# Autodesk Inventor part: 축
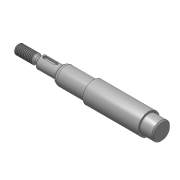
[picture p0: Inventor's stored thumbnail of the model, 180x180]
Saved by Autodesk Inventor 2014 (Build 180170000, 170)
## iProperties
Created: 2015-11
Part Number: 축
Material: 강철, 연강
Document SubType Name: Modeling
Designer: mduedu
Density: 1 g/cm^3
Appearance: Steel
Author: mduedu
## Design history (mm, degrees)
sketch "스케치1"
  geometry: L1 (-86, 0)-(86, 0); L2 (-86, 0)-(-86, 4); L3 (-86, 4)-(-70.732, 4); L4 (-70.732, 4)-(-69, 3); L5 (-69, 3)-(-67, 3); L6 (-67, 3)-(-67, 5); L7 (-67, 5)-(-49, 5); L8 (-49, 5)-(-49, 6.55); L9 (-47.355, 7.5)-(-23, 7.5); L10 (-23, 7.5)-(-23, 9); L11 (0, 0)-(0, 9); L12 (86, 4)-(70.732, 4); L13 (70.732, 4)-(69, 3); L14 (69, 3)-(67, 3); L15 (67, 3)-(67, 5); L16 (67, 5)-(49, 5); L17 (23, 7.5)-(23, 9); L18 (86, 0)-(86, 4); L19 (-23, 9)-(23, 9); L20 (-49, 6.55)-(-47.355, 7.5); L21 (47.355, 7.5)-(23, 7.5); L22 (49, 6.55)-(47.355, 7.5); L23 (49, 5)-(49, 6.55); 1 further point
  constraints: 46 end point, 10 symmetric about line, 6 perpendicular, 5 parallel, 2 midpoint, 1 coincident, 1 horizontal
  dimensions: "d0" = 172 distance of L1.start L1.end (derived); "d1" = 8 diameter of L3 L1; "d2" = 30 deg angle of L4 L5; "d3" = 6 diameter of L5 L1; "d4" = 10 diameter of L7 L1; "d5" = 15 diameter of L9 L1; "d6" = 18 diameter of L19 L1; "d8" = 18 distance of L6.end L7.end; "d9" = 46 distance of L10.end L17.end; "d10" = 2 distance of L4.end L5.end; "d11" = 17 distance from line of L4.end L2; "d16" = 13.1 diameter of L8.end L1; "d17" = 30 deg angle of L20 L9; "d18" = 26 distance between parallel lines of L10 L8
revolve "회전1" sketch "스케치1" stored, may be unused: angle "d12" = 90 deg
chamfer "모따기1" distance "d13" = 1; stored, may be unused: second distance "d14" = 2, angle "d15" = 45 deg
fillet "모깎기3" dims "d35" = 4
node "작업 평면1"
sketch "스케치2" dims "d23" = 12
  geometry: L1 (-5.5, 1.5)-(3.5, 1.5); L2 (3.5, 1.5)-(3.5, -1.5); L3 (3.5, -1.5)-(-5.5, -1.5); L4 (-5.5, -1.5)-(-5.5, 1.5); L5 (-9, -4)-(-9, 4) reference; 3 further points
  constraints: 8 end point, 2 midpoint, 2 parallel, 2 vertical alignment, 1 horizontal, 1 perpendicular, 4 other
  dimensions: "d21" = 3 distance between parallel lines of L3 L1; "d24" = 2 dimension on L5
extrude "돌출1" cut sketch "스케치2" distance "d25" = 1.8; taper "d26" = 0 deg
feature "스레드1" dims "d27" = 10, "d28" = 0
feature "스레드2" dims "d29" = 10, "d30" = 0
chamfer "모따기2" distance "d31" = 1; stored, may be unused: second distance "d32" = 2, angle "d33" = 45 deg
fillet "모깎기2" dims "d34" = 0.3
node "작업 평면2"
sketch "스케치3"
  geometry: C1 r 7.5 at (0, 0) reference; 1 further point
extrude "돌출2" cut sketch "스케치3" stored distance "d37" = 10; taper "d38" = 0 deg
chamfer "모따기3" distance "d39" = 1; stored, may be unused: second distance "d40" = 2, angle "d41" = 45 deg
node "솔리드1"
mirror "대칭1"
node "절단 모서리 투영1"
other parameters: "d36" = 11
